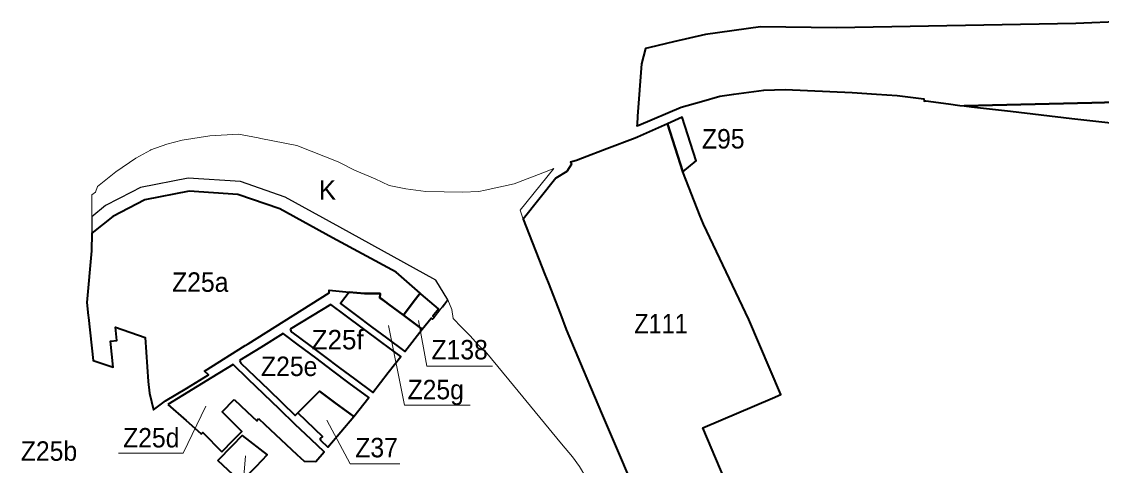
# Model space of a CAD drawing. Extents: x -650276 to -642489, y -1074311 to -1066658.
# Drawn here: x -650081 to -648750, y -1069712 to -1069165 of the extents above; entities that cross this region are included whole.
import ezdxf

# ---------------------------------------------------------------- set-up
doc = ezdxf.new("R2010")
doc.units = 0
doc.header["$LTSCALE"] = 9.6
for name, color, linetype, lineweight in [('3', 7, 'Continuous', 40), ('4', 7, 'Continuous', 40), ('42', 7, 'Continuous', 25), ('44', 7, 'Continuous', 40), ('45', 7, 'Continuous', 40), ('46', 7, 'Continuous', 13), ('47', 7, 'Continuous', 13), ('48', 7, 'Continuous', 35), ('59', 7, 'Continuous', 13)]:
    doc.layers.add(name, color=color, linetype=linetype, lineweight=lineweight)

msp = doc.modelspace()

# ---------------------------------------------------------------- linework, layer by layer
at = {"layer": '3'}
for points in [[(-649639.18, -1069505.96), (-649637.69, -1069506.15), (-649628.36, -1069513.11), (-649609.93, -1069526.87), (-649598.004, -1069510.814), (-649589.257, -1069499.905), (-649619, -1069474), (-649697.525, -1069431.522), (-649762.488, -1069395.854), (-649814.067, -1069377.972), (-649874.391, -1069373.859), (-649929.015, -1069384.784), (-649968.465, -1069405.189), (-649994.293, -1069425.949), (-649994.53, -1069447.61), (-650000.59, -1069511.15), (-649998.81, -1069527.07), (-649998.5, -1069529.88), (-649992.59, -1069582.88), (-649967.81, -1069590.74), (-649971.38, -1069558.79), (-649963.43, -1069557.91), (-649965.26, -1069541.51), (-649928.48, -1069554.57), (-649927.3, -1069572.44)], [(-649927.3, -1069572.44), (-649924.62, -1069608.53), (-649923.17, -1069623.14), (-649918.35, -1069643.45), (-649918.35, -1069643.45), (-649903.292, -1069632.541), (-649877.129, -1069617.006), (-649850.24, -1069600.295), (-649855.34, -1069595.8), (-649805.22, -1069564.32), (-649801.49, -1069561.98), (-649701.57, -1069499.21), (-649701.7, -1069495.89), (-649677.02, -1069498.32), (-649658.01, -1069500.19), (-649647.45, -1069500.23), (-649638.81, -1069500.26), (-649639.18, -1069505.96)], [(-649677.02, -1069498.32), (-649687.77, -1069512.44), (-649667.74, -1069527.4), (-649649.31, -1069541.16)], [(-649639.18, -1069505.96), (-649638.81, -1069500.26), (-649647.45, -1069500.23), (-649658.01, -1069500.19), (-649677.02, -1069498.32)], [(-649707.19, -1069577.81), (-649688.76, -1069591.57), (-649670.34, -1069605.34), (-649647.93, -1069622.07), (-649628.8, -1069597.67), (-649613.37, -1069577.98), (-649636.83, -1069560.47), (-649659.26, -1069543.71), (-649681.7, -1069526.96), (-649699.72, -1069513.5), (-649722.6, -1069527.61), (-649749.62, -1069544.29)], [(-649609.93, -1069526.87), (-649628.36, -1069513.11), (-649637.69, -1069506.15), (-649639.18, -1069505.96)], [(-649649.31, -1069541.16), (-649630.88, -1069554.92), (-649608.44, -1069571.69), (-649586.82, -1069544.11), (-649609.93, -1069526.87)], [(-649758.29, -1069549.64), (-649785.72, -1069566.56), (-649812.08, -1069582.83)], [(-649671.39, -1069651.93), (-649652.88, -1069628.36), (-649677.124, -1069610.681), (-649696.91, -1069595.47), (-649718.13, -1069579.63), (-649739.75, -1069563.48), (-649758.29, -1069549.64)], [(-649749.62, -1069544.29), (-649748.89, -1069546.2), (-649747.5, -1069547.71), (-649725.62, -1069564.05), (-649707.19, -1069577.81)], [(-649788.91, -1069654.4), (-649781.09, -1069661.69), (-649761.34, -1069680.08), (-649741.61, -1069698.46), (-649732.52, -1069706.92), (-649717.884, -1069707.295), (-649707.985, -1069695.508), (-649723.97, -1069680.13), (-649743.41, -1069661.43), (-649762.85, -1069642.73), (-649782.03, -1069624.28), (-649801.48, -1069605.57), (-649820.02, -1069587.73), (-649846.38, -1069603.8), (-649900.64, -1069636.78)], [(-649812.08, -1069582.83), (-649811.52, -1069584.44), (-649810.49, -1069585.81), (-649793.12, -1069602.51), (-649776.54, -1069618.46), (-649759.97, -1069634.4)], [(-649740.23, -1069647.14), (-649713.73, -1069620.32), (-649713.73, -1069620.32), (-649693.63, -1069635.33), (-649671.39, -1069651.93)], [(-649833.94, -1069695.239), (-649819.98, -1069680.92), (-649809.47, -1069670.13), (-649833.38, -1069646.08), (-649818.71, -1069630.64)], [(-649818.71, -1069630.64), (-649802.9, -1069645.96), (-649791, -1069657), (-649788.91, -1069654.4)], [(-649759.97, -1069634.4), (-649743.39, -1069650.35), (-649740.23, -1069647.14)], [(-649900.64, -1069636.78), (-649877.82, -1069656.83), (-649859.96, -1069672.53)], [(-649859.96, -1069672.53), (-649859.17, -1069673.22), (-649857.49, -1069671.46), (-649833.94, -1069695.239)]]:
    msp.add_lwpolyline(points, dxfattribs=at)
for points in [[(-649713.73, -1069620.32), (-649713.73, -1069620.32), (-649740.23, -1069647.14), (-649709.94, -1069676.28), (-649712.54, -1069678.98), (-649712.89, -1069679.87), (-649712.51, -1069680.75), (-649703.15, -1069689.75), (-649671.39, -1069651.93), (-649693.63, -1069635.33)], [(-649838.99, -1069706.15), (-649820.64, -1069687.33), (-649808.96, -1069675.34), (-649777.94, -1069699.2), (-649792.13, -1069713.65), (-649807.66, -1069729.46), (-649810.41, -1069732.28), (-649819.9, -1069723.61)]]:
    msp.add_lwpolyline(points, close=True, dxfattribs=at)
at = {"layer": '4'}
for points in [[(-649571.94, -1069529.24), (-649573.922, -1069527.657), (-649567, -1069519), (-649588, -1069501), (-649589.257, -1069499.905), (-649597.935, -1069510.728)], [(-649597.997, -1069510.805), (-649598.004, -1069510.814), (-649609.93, -1069526.87), (-649586.82, -1069544.11)], [(-649597.935, -1069510.728), (-649597.763, -1069510.865), (-649597.997, -1069510.805)], [(-649586.82, -1069544.11), (-649576.071, -1069530.398), (-649574.1, -1069531.97), (-649571.94, -1069529.24)]]:
    msp.add_lwpolyline(points, dxfattribs=at)
at = {"layer": '42'}
msp.add_lwpolyline([(-649561.91, -1069516.78), (-649555.16, -1069508.07), (-649570.03, -1069483.83), (-649688.625, -1069418.156), (-649755.971, -1069381.179), (-649810.846, -1069362.154), (-649875.434, -1069357.751), (-649934.363, -1069369.537), (-649945.397, -1069375.277), (-649977.239, -1069391.714), (-649994.329, -1069405.451), (-649994.293, -1069425.949), (-649994.53, -1069447.61), (-650000.59, -1069511.15), (-649992.59, -1069582.88), (-649967.81, -1069590.74), (-649971.38, -1069558.79), (-649963.43, -1069557.91), (-649965.26, -1069541.51), (-649928.48, -1069554.57), (-649924.62, -1069608.53), (-649923.17, -1069623.14), (-649918.35, -1069643.45), (-649903.292, -1069632.541), (-649877.129, -1069617.006), (-649850.24, -1069600.295), (-649855.34, -1069595.8), (-649805.22, -1069564.32), (-649701.57, -1069499.21), (-649701.7, -1069495.89), (-649677.02, -1069498.32), (-649658.01, -1069500.19), (-649647.45, -1069500.23), (-649638.81, -1069500.26), (-649639.18, -1069505.96), (-649628.36, -1069513.11), (-649609.93, -1069526.87), (-649598.004, -1069510.814), (-649589.257, -1069499.905), (-649567, -1069519), (-649573.922, -1069527.657), (-649571.94, -1069529.24), (-649555.16, -1069508.07)], close=True, dxfattribs=at)
at = {"layer": '44'}
for points in [[(-648721.315, -1069164.952), (-648781.015, -1069167.44), (-649076.02, -1069172.683), (-649169.781, -1069171.432), (-649237.512, -1069180.731), (-649277.021, -1069189.913), (-649306.455, -1069196.754), (-649311.633, -1069197.958), (-649316.47, -1069216.91), (-649321.32, -1069281.47), (-649322.09, -1069291.73), (-649322.22, -1069293.54), (-649319.72, -1069292.47), (-649267.5, -1069270.41), (-649242.5, -1069263.3), (-649220.18, -1069257.03), (-649202.63, -1069254.4), (-649165.62, -1069249.43), (-649139.63, -1069248.73), (-649056.95, -1069252.55), (-649026.955, -1069254.366), (-649001.3, -1069255.92), (-648968.49, -1069260.36), (-648968.05, -1069263.06), (-648965.8, -1069262.75), (-648937.91, -1069266.51), (-648924.13, -1069268.21), (-648918.889, -1069268.875)], [(-648918.889, -1069268.875), (-648761.189, -1069265.035), (-648666.827, -1069262.738), (-648665.007, -1069262.694)], [(-648666.827, -1069262.738), (-648761.189, -1069265.035), (-648918.889, -1069268.875), (-648909.86, -1069270.02), (-648861.49, -1069275.34), (-648785.92, -1069284.2), (-648730.66, -1069290.43), (-648730.66, -1069290.43), (-648655.53, -1069297.18), (-648650.06, -1069296.39), (-648636.85, -1069294.49)]]:
    msp.add_lwpolyline(points, dxfattribs=at)
at = {"layer": '45'}
msp.add_lwpolyline([(-649265.774, -1069350.068), (-649249.069, -1069336.66), (-649266.331, -1069282.804), (-649284.695, -1069291.033)], close=True, dxfattribs=at)
msp.add_lwpolyline([(-649202.99, -1069754.99), (-649241.11, -1069665.9), (-649155.082, -1069629.097), (-649144.57, -1069624.6), (-649184.1, -1069532.2), (-649240.202, -1069414.528), (-649244.08, -1069404.753), (-649265.774, -1069350.068), (-649284.695, -1069291.033), (-649321.69, -1069307.61), (-649324.3, -1069308.59), (-649359.48, -1069321.82), (-649389.4, -1069333.35), (-649396.52, -1069336.09), (-649403.92, -1069338.26), (-649403.03, -1069340.66), (-649408.81, -1069349.89), (-649422.19, -1069357.99), (-649462.25, -1069408.32), (-649435.578, -1069476.772), (-649435.578, -1069476.772), (-649431.761, -1069486.57), (-649416.52, -1069525.68), (-649409.355, -1069544.517), (-649388.438, -1069594.296), (-649379.32, -1069615.71), (-649364.44, -1069650.55), (-649312.03, -1069773.33)], dxfattribs=at)
at = {"layer": '47'}
for points in [[(-649509.42, -1069372.61), (-649517.17, -1069374.3), (-649537.32, -1069375.23), (-649582.25, -1069374.51), (-649607.18, -1069370.92), (-649627.76, -1069366.8), (-649645.03, -1069358.8), (-649670.23, -1069347.9), (-649688.73, -1069338.7), (-649690.59, -1069337.98), (-649741.5, -1069317.74), (-649785.8, -1069308.94), (-649789, -1069308.31), (-649813.3, -1069303.66), (-649848.62, -1069305.95), (-649882.93, -1069311.1), (-649901.58, -1069316.01), (-649921.54, -1069323.03), (-649922.11, -1069323.35), (-649939.81, -1069333.47), (-649964.53, -1069350.02), (-649987.12, -1069368.03), (-649989.67, -1069375.36), (-649994.38, -1069378.33), (-649994.35, -1069394.43), (-649994.34, -1069398.8), (-649994.329, -1069405.451), (-649977.239, -1069391.714), (-649945.397, -1069375.277), (-649934.363, -1069369.537), (-649875.434, -1069357.751), (-649810.846, -1069362.154), (-649755.971, -1069381.179), (-649688.625, -1069418.156), (-649570.03, -1069483.83)], [(-649424.8, -1069346.14), (-649438.17, -1069351.27), (-649473.35, -1069364.76), (-649473.35, -1069364.76), (-649509.42, -1069372.61)], [(-649431.761, -1069486.57), (-649435.578, -1069476.772), (-649435.578, -1069476.772), (-649462.25, -1069408.32), (-649466.045, -1069397.373), (-649424.8, -1069346.14)], [(-649570.03, -1069483.83), (-649555.16, -1069508.07), (-649550.53, -1069519.68)], [(-649409.349, -1069544.532), (-649409.355, -1069544.517), (-649416.52, -1069525.68), (-649431.761, -1069486.57)], [(-649550.53, -1069519.68), (-649548.881, -1069530.963), (-649538.49, -1069541.54)], [(-649538.49, -1069541.54), (-649527.84, -1069552.16), (-649517.81, -1069563.27), (-649507.23, -1069573.85), (-649474.46, -1069613.59), (-649415.12, -1069685.26), (-649401.77, -1069701.47), (-649392.85, -1069713.53), (-649385.25, -1069726.48), (-649379.49, -1069740.04), (-649376.01, -1069754.58), (-649372.2, -1069772.58), (-649370.94, -1069787.45), (-649372.56, -1069802.33), (-649372.56, -1069802.33), (-649338, -1069822), (-649350.222, -1069920.873), (-649310.738, -1069929.342), (-649296.851, -1069931.092)], [(-649379.32, -1069615.71), (-649407.002, -1069550.701), (-649409.349, -1069544.532)], [(-649202.375, -1070030.469), (-649239.635, -1069943.094), (-649246.81, -1069926.27), (-649246.81, -1069926.27), (-649312.03, -1069773.33), (-649364.44, -1069650.55), (-649379.32, -1069615.71)]]:
    msp.add_lwpolyline(points, dxfattribs=at)
at = {"layer": '59'}
for points in [[(-649527.746, -1069637.974), (-649608.666, -1069637.974), (-649628.441, -1069539.635)], [(-649500.234, -1069589.798), (-649581.154, -1069589.798), (-649591.594, -1069533.245)], [(-649961.194, -1069696.966), (-649881.648, -1069696.966), (-649853.499, -1069639.046), (-649881.648, -1069696.966), (-649881.648, -1069696.966)], [(-649614.407, -1069710.017), (-649675.69, -1069710.017), (-649704.435, -1069656.13)], [(-649890.273, -1069770.557), (-649810.727, -1069770.557), (-649804.906, -1069700.153), (-649810.727, -1069770.557), (-649810.727, -1069770.557)]]:
    msp.add_lwpolyline(points, dxfattribs=at)

# ---------------------------------------------------------------- texts
at = {"layer": '44', "width": 0.95}
msp.add_text('Z95', height=24, dxfattribs=at).set_placement((-649242.024, -1069321.399))
at = {"layer": '46', "width": 0.9}
msp.add_text('Z111', height=24, dxfattribs=at).set_placement((-649325.444, -1069549.35))
msp.add_text('Z111', height=24, dxfattribs=at).set_placement((-649325.444, -1069549.35))
at = {"layer": '48'}
msp.add_text('K', height=24, dxfattribs=at).set_placement((-649714.485, -1069384.456))
msp.add_text('K', height=24, dxfattribs=at).set_placement((-649714.485, -1069384.456))
at = {"layer": '59', "width": 0.95}
for s, p in [('Z25a', (-649895.305, -1069498.073)), ('Z138', (-649575.524, -1069581.383)), ('Z25e', (-649785.641, -1069601.889)), ('Z25g', (-649605.002, -1069630.542)), ('Z25d', (-649955.718, -1069689.936)), ('Z25b', (-650081.8, -1069706.363)), ('Z37', (-649669.466, -1069702.084))]:
    msp.add_text(s, height=24, dxfattribs=at).set_placement(p)
at = {"layer": '59'}
msp.add_text('Z25f', height=24, dxfattribs=at).set_placement((-649723.257, -1069569.036))

doc.saveas('drawing.dxf')
